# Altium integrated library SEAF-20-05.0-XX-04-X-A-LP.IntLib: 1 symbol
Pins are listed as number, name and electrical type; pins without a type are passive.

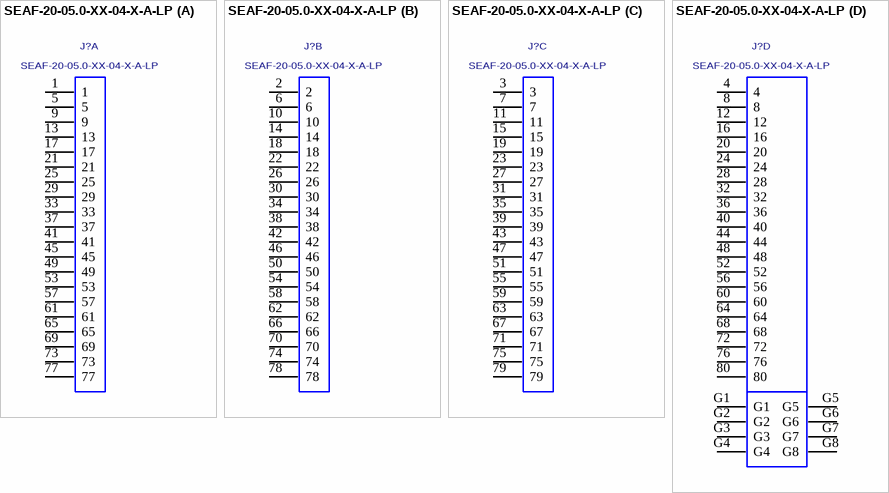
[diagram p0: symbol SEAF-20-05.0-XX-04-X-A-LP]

## SEAF-20-05.0-XX-04-X-A-LP
designator J?
Socket Array Assembly, Surface Mount With -LP Option, 0.050" Pitch, 80 Pins.; MANUFACTURER: SAMTEC
footprint SEAF-20-05.0-XX-04-X-A-LP
footprint SEAF-20-05.0-XX-04-X-A-LP
part A pins: 1, 5, 9, 13, 17, 21, 25, 29, 33, 37, 41, 45, 49, 53, 57, 61, 65, 69, 73, 77
part B pins: 2, 6, 10, 14, 18, 22, 26, 30, 34, 38, 42, 46, 50, 54, 58, 62, 66, 70, 74, 78
part C pins: 3, 7, 11, 15, 19, 23, 27, 31, 35, 39, 43, 47, 51, 55, 59, 63, 67, 71, 75, 79
part D pins: 4, 8, 12, 16, 20, 24, 28, 32, 36, 40, 44, 48, 52, 56, 60, 64, 68, 72, 76, 80, G1, G2, G3, G4, G5, G6, G7, G8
